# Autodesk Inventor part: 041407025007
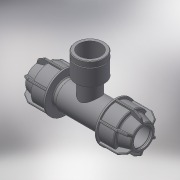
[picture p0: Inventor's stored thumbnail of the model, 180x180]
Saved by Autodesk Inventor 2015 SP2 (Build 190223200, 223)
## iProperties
Created: 2017-08
Part Number: 041407025007
Material: Generic
Description: PLASSON IRRIFIT TEE FEMALE ADAPTOR 25-3/4"-25
Document SubType Name: Modeling
Designer: KIM
Density: 1 g/cm^3
Appearance: Default
Author: KIM
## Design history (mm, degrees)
derived "041407.ipt"
feature "Solid1::041407.ipt"
feature "Solid2::041407.ipt"
tag "TaggingFeature1"
body "Solid1"
other parameters: "d1" = 25, "d2" = 31, "d4" = 15 deg, "d5" = 29.45, "d6" = 11.78, "d10" = 45, "d16" = 25.5, "d17" = 1.55, "d22" = 32.5, "d24" = 1.55, "d25" = 40.5, "d26" = 33.75, "d27" = 1.55, "d28" = 135 deg, "d29" = 0.93, "d31" = 1.25, "d46" = 150 deg, "d49" = 2.25, "d50" = 0, "d58" = 0.75, "d61" = 360 deg, "d63" = 22.5, "d64" = 53.5, "d80" = 35.75, "d81" = 0.25, "d94" = 49, "d96" = 31.3521, "d108" = 0.75, "d113" = 16.8819, "d115" = 20.4, "d117" = 21.7053, "d118" = 3.1, "d119" = 17, "d120" = 24.117, "d121" = 0.48234, "d122" = 5.1, "d123" = 3.1, "d128" = 31.3521, "d130" = 0, "d132" = 0, "d_" = 25, "G_" = 24.117, "E_" = 45, "H_" = 107, "l_" = 31, "l_1" = 17, "A_" = 49
